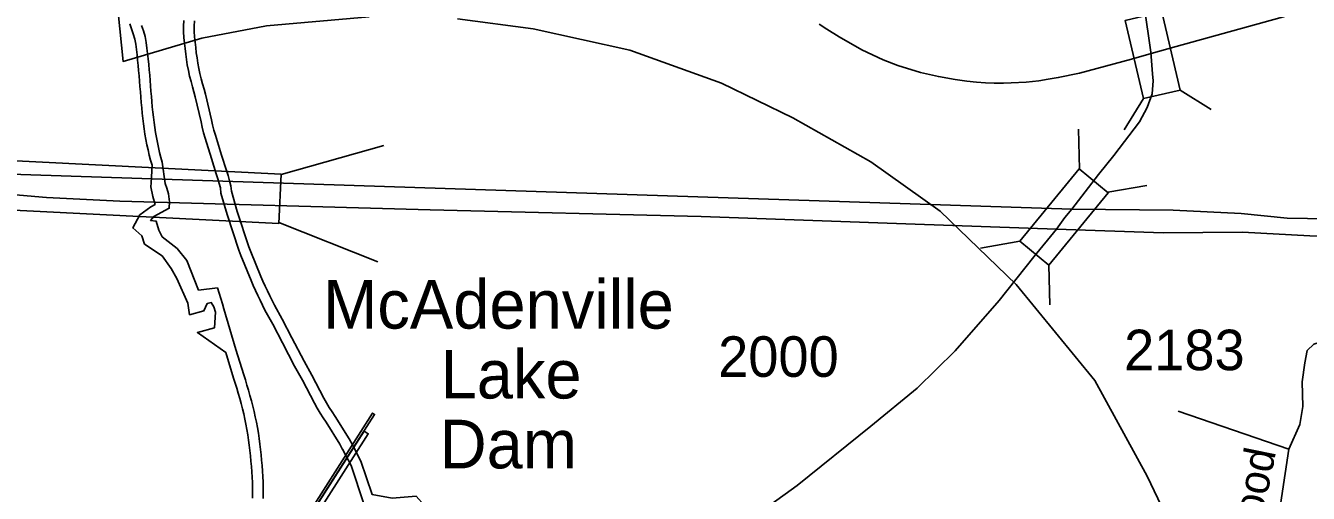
# Model space of a CAD drawing. Extents: x 1364363 to 1407445, y 538563 to 573342.
# Drawn here: x 1379352 to 1383308, y 556667 to 558110 of the extents above; entities that cross this region are included whole.
import ezdxf

# ---------------------------------------------------------------- set-up
doc = ezdxf.new("R2010")
doc.units = 0
for name, color, linetype in [('Exist Boundary Political City Limit New', 7, 'Continuous'), ('Exist Hydrographic Buffer Line', 7, 'Continuous'), ('Exist Hydrographic Creek Double Shore', 7, 'Continuous'), ('Exist Hydrographic Lake Dam', 7, 'Continuous'), ('Exist Railroad Mainline', 7, 'Continuous'), ('Exist Road Primary Interstate Divided Center Attributed', 7, 'Continuous'), ('Exist Road Primary Interstate Structure Standard Bridge CELL', 7, 'Continuous'), ('Exist Road Secondary Structure Standard Bridge CELL', 7, 'Continuous'), ('Exist Road Secondary Type 51 Attributed', 7, 'Continuous'), ('Exist Road Secondary Type 51 Label', 7, 'Continuous'), ('Exist Road Secondary Type 51 Number Label', 7, 'Continuous')]:
    doc.layers.add(name, color=color, linetype=linetype)

msp = doc.modelspace()

# ---------------------------------------------------------------- linework, layer by layer
at = {"layer": 'Exist Boundary Political City Limit New'}
for points in [[(1379628.6, 558241.4), (1379652.8, 557999.4), (1379895.8, 558071.1), (1380094.6, 558108.9), (1380411.5, 558136.3)], [(1380683.5, 558130.6), (1380917, 558099.8), (1381215.6, 558033.5), (1381497.8, 557931.8), (1381717.6, 557825.1), (1381958.9, 557689.9), (1382171.9, 557537.4), (1382407.2, 557310.6), (1382649.2, 557015.3), (1382811.1, 556719.8), (1382951.1, 556424.8), (1383046.6, 556108.5), (1383105.9, 555785.2), (1383120, 555490.8), (1383095.2, 555175.1)]]:
    msp.add_lwpolyline(points, dxfattribs=at)
at = {"layer": 'Exist Hydrographic Buffer Line'}
for points in [[(1379709.6, 558110.4), (1379715.3, 558094), (1379720.8, 558075.8), (1379724.1, 558057.2), (1379726.4, 558040), (1379728.4, 558023.3), (1379730.2, 558006.7), (1379731.9, 557990.2), (1379733.4, 557973.5), (1379734.8, 557957), (1379736.1, 557940.6), (1379737.4, 557924.2), (1379738.8, 557907.8), (1379740.1, 557891.5), (1379741.4, 557875.3), (1379742.9, 557859.2), (1379744.5, 557843.1), (1379746.3, 557827.1), (1379748.2, 557811.2), (1379750.2, 557795.4), (1379752.6, 557780), (1379755.3, 557764.5), (1379758.4, 557748.9), (1379761.7, 557733.5), (1379765.4, 557718.1), (1379769.3, 557703), (1379773.4, 557688.8), (1379782.2, 557622.5), (1379787.9, 557608.5), (1379793.1, 557591.1), (1379796.4, 557566), (1379795.3, 557546), (1379747.4, 557521.2), (1379737.6, 557508.5), (1379754.4, 557506.5), (1379763, 557478.7), (1379773, 557458.1), (1379819.1, 557421.8), (1379849.1, 557385.3), (1379885.7, 557293.7), (1379943.5, 557300.7), (1379949.4, 557284.1), (1379954.6, 557267.4), (1379959.3, 557251.2), (1379963.7, 557235.4), (1379982, 557172.7), (1380000.7, 557110.3), (1380024.7, 557032.2), (1380029.8, 557016.5), (1380034.7, 557000.5), (1380039.5, 556984.5), (1380044.1, 556968.4), (1380048.5, 556952.1), (1380052.7, 556935.8), (1380056.8, 556919.3), (1380060.5, 556902.7), (1380063.9, 556886.1), (1380067.1, 556869.4), (1380069.9, 556852.5), (1380072.3, 556835.6), (1380074.4, 556818.9), (1380076.4, 556802.2), (1380078.1, 556785.6), (1380079.7, 556769.1), (1380081.3, 556752.6), (1380082.8, 556735.6), (1380083.7, 556718.4), (1380084.4, 556701.3), (1380084.6, 556684.4), (1380084.7, 556667.8), (1380084.7, 556651.1)], [(1379839.9, 558125.4), (1379839.3, 558108.3), (1379839.5, 558090.5), (1379840.5, 558072.7), (1379842.1, 558055.4), (1379844, 558038.7), (1379846, 558022.1), (1379848.2, 558005.3), (1379850.8, 557988.2), (1379854, 557970.9), (1379857.9, 557953.7), (1379862.2, 557937.3), (1379866.4, 557921.3), (1379870.8, 557905.2), (1379875, 557889.8), (1379893.6, 557812.5), (1379896.3, 557796.2), (1379901.2, 557778.4), (1379906.1, 557762.2), (1379925.4, 557699.7), (1379940.3, 557652.7), (1379945.1, 557637.4), (1379949.5, 557622.6), (1379952.7, 557609.5), (1379954.6, 557592.5), (1379973.6, 557526.6), (1380009.8, 557416.7), (1380015.6, 557400.1), (1380047.4, 557323.2), (1380054.2, 557307.8), (1380061.1, 557292.5), (1380068.1, 557277.3), (1380075.3, 557262.2), (1380082.5, 557247.2), (1380090.3, 557231.4), (1380114.6, 557188.9), (1380144.1, 557131.4), (1380181.8, 557058.6), (1380205.7, 557015.5), (1380243, 556944.8), (1380251.1, 556929.5), (1380260.2, 556914.3), (1380269.7, 556899.7), (1380278.8, 556886.3), (1380321.3, 556818.3), (1380329.8, 556802.4)], [(1381262.6, 555900.5), (1381213.8, 555976.4), (1381107.2, 556071.9), (1381035.1, 556160.7), (1380901, 556244.5), (1380797.6, 556336.5), (1380656.5, 556442.3), (1380581.1, 556581.7), (1380543.3, 556623.7), (1380481.3, 556618.9), (1380395.5, 556634.5), (1380356.1, 556752.7), (1380329.8, 556802.5)]]:
    msp.add_lwpolyline(points, dxfattribs=at)
at = {"layer": 'Exist Hydrographic Creek Double Shore'}
for points in [[(1379673.2, 558115), (1379678.7, 558099.4), (1379684.1, 558083.9), (1379688.8, 558068.2), (1379691.7, 558052.1), (1379693.9, 558035.9), (1379695.8, 558019.6), (1379697.6, 558003.3), (1379699.2, 557987), (1379700.7, 557970.7), (1379702.1, 557954.3), (1379703.4, 557937.9), (1379704.7, 557921.5), (1379706.1, 557905.1), (1379707.4, 557888.8), (1379708.7, 557872.4), (1379710.3, 557856), (1379711.9, 557839.7), (1379713.7, 557823.4), (1379715.6, 557807.1), (1379717.8, 557790.8), (1379720.2, 557774.6), (1379723.1, 557758.4), (1379726.3, 557742.3), (1379729.7, 557726.2), (1379733.5, 557710.2), (1379737.6, 557694.4), (1379742.2, 557678.7), (1379739.3, 557624.5), (1379738.1, 557612.7), (1379744.5, 557582.2), (1379751.5, 557557.6), (1379738.7, 557550.3), (1379704.7, 557525.8), (1379682.4, 557485.7), (1379710.8, 557461.4), (1379718.6, 557435.8), (1379773.8, 557399), (1379801.1, 557360), (1379818.9, 557329.3), (1379852.9, 557253.9), (1379857.9, 557217.7), (1379901.9, 557229.4), (1379911.9, 557252.2), (1379924.7, 557255), (1379932.8, 557241.6), (1379937.3, 557225.9), (1379934.4, 557177.5), (1379882, 557162.5), (1379969.4, 557100.8), (1379993.4, 557022.3), (1379998.5, 557006.7), (1380003.3, 556991), (1380008, 556975.3), (1380012.5, 556959.5), (1380016.8, 556943.7), (1380020.9, 556927.8), (1380024.8, 556911.9), (1380028.4, 556895.8), (1380031.7, 556879.7), (1380034.8, 556863.6), (1380037.4, 556847.4), (1380039.8, 556831.2), (1380041.8, 556814.9), (1380043.8, 556798.6), (1380045.4, 556782.3), (1380047.1, 556765.9), (1380048.6, 556749.6), (1380050, 556733.3), (1380051, 556716.9), (1380051.6, 556700.5), (1380051.8, 556684.1), (1380051.9, 556667.7), (1380051.9, 556651.3)], [(1379872.7, 558124.3), (1379872.2, 558107.9), (1379872.3, 558091.5), (1379873.2, 558075.1), (1379874.7, 558058.8), (1379876.6, 558042.5), (1379878.5, 558026.2), (1379880.7, 558009.9), (1379883.1, 557993.7), (1379886.1, 557977.5), (1379889.8, 557961.5), (1379893.9, 557945.6), (1379898.1, 557929.8), (1379902.4, 557913.9), (1379906.8, 557898.1), (1379925.8, 557819), (1379928.3, 557803.3), (1379932.8, 557787.5), (1379937.5, 557771.7), (1379956.7, 557709.5), (1379971.6, 557662.6), (1379976.5, 557646.9), (1379981.1, 557631.1), (1379985, 557615.3), (1379986.9, 557598.9), (1380004.9, 557536.3), (1380040.9, 557427.2), (1380046.2, 557411.7), (1380077.6, 557336.1), (1380084.2, 557321.1), (1380090.9, 557306.1), (1380097.8, 557291.2), (1380104.9, 557276.3), (1380112, 557261.5), (1380119.2, 557246.8), (1380143.4, 557204.5), (1380173.3, 557146.5), (1380210.7, 557074.1), (1380234.6, 557031.1), (1380272, 556960.2), (1380279.7, 556945.7), (1380288.1, 556931.6), (1380297, 556917.8), (1380306.3, 556904.2), (1380349.7, 556834.7), (1380358.7, 556817.9)], [(1381290.2, 555918.3), (1381239, 555997.9), (1381131, 556094.6), (1381057.1, 556185.6), (1380920.7, 556270.9), (1380818.4, 556361.9), (1380682, 556464.3), (1380608.1, 556600.8), (1380556.9, 556657.6), (1380483, 556652), (1380420.5, 556663.3), (1380386.4, 556765.7), (1380358.7, 556817.9)]]:
    msp.add_lwpolyline(points, dxfattribs=at)
at = {"layer": 'Exist Hydrographic Lake Dam'}
for points in [[(1380029.7, 556285.2), (1380428.4, 556910.3), (1380422.2, 556914.3), (1380023.6, 556289.1)], [(1380062.5, 556336.5), (1380395.7, 556859), (1380409, 556850.5), (1380075.8, 556328)]]:
    msp.add_lwpolyline(points, close=True, dxfattribs=at)
at = {"layer": 'Exist Railroad Mainline'}
msp.add_lwpolyline([(1381799.6, 558114.6), (1381822.7, 558098.5), (1381861.2, 558075.3), (1381930.3, 558035.1), (1381996.6, 558004.4), (1382042, 557987.1), (1382111.6, 557965.4), (1382166.8, 557952.6), (1382219.1, 557943.2), (1382254.8, 557938.6), (1382284.9, 557935.2), (1382312.3, 557933.1), (1382338.5, 557932.3), (1382367.7, 557932.6), (1382391.7, 557933.1), (1382437.4, 557935.5), (1382477, 557939.8), (1382505.3, 557944.1), (1382536.6, 557949.5), (1382601.5, 557963.3), (1382762, 558006.2), (1382823, 558023.5), (1382900.5, 558045.5), (1383267.6, 558147.2)], dxfattribs=at)
at = {"layer": 'Exist Road Primary Interstate Divided Center Attributed'}
for points in [[(1382578.3, 557543.3), (1378993.5, 557662), (1378353.6, 557700.7), (1377951.9, 557715.7), (1377613, 557708.6)], [(1378009.8, 557639.5), (1378088.7, 557639.5), (1378267.6, 557630.8), (1379261.7, 557592.6), (1379417.1, 557579), (1379642.8, 557567.9)], [(1379642.8, 557567.9), (1380599.9, 557541.4), (1381435, 557521.1), (1382094.8, 557497), (1382531.5, 557481.6)], [(1385949.5, 557261.4), (1385838.7, 557297.2), (1385700.2, 557335.7), (1385555.5, 557374.9), (1385363.2, 557413.7), (1385252.4, 557436.1), (1385141.6, 557451), (1385049.2, 557464.5), (1384710.8, 557467.7), (1384340.5, 557484.4), (1383867.5, 557505.6), (1383242.8, 557515.9), (1383100.7, 557529.7), (1382890.4, 557540.7), (1382578.3, 557543.3)], [(1382531.5, 557481.6), (1382859.6, 557470.5), (1383105.1, 557472.7), (1383312.1, 557460.7), (1383713, 557449.7), (1383905.8, 557445.3), (1384433.1, 557402.9), (1384673, 557367.4), (1384806.8, 557349.5), (1384968.4, 557322.6), (1385057.7, 557304.7), (1385197, 557267.4), (1385401.7, 557212.1), (1385543.2, 557173.3), (1385689.4, 557131.5), (1385878, 557074.8)]]:
    msp.add_lwpolyline(points, dxfattribs=at)
at = {"layer": 'Exist Road Primary Interstate Structure Standard Bridge CELL'}
for p, q in [((1380140.6, 557650.2), (1380456.5, 557739.5)), ((1380133.1, 557501.9), (1380438.5, 557381.4))]:
    msp.add_line(p, q, dxfattribs=at)
msp.add_lwpolyline([(1379178.3, 557699.3), (1380140.6, 557650.9), (1380133, 557499.1), (1379170.7, 557547.5)], close=True, dxfattribs=at)
at = {"layer": 'Exist Road Secondary Structure Standard Bridge CELL'}
for p, q in [((1383008.4, 557851.2), (1382912.3, 557910.9)), ((1382739.8, 557788.4), (1382799.5, 557884.6)), ((1382601.6, 557667.3), (1382598.9, 557790.1)), ((1382689.1, 557595.4), (1382810.1, 557616.7)), ((1382296.9, 557423.3), (1382417.9, 557444.5)), ((1382510.1, 557248.2), (1382507.4, 557371))]:
    msp.add_line(p, q, dxfattribs=at)
for points in [[(1382799.5, 557884.6), (1382743.1, 558125.9), (1382855.8, 558152.3), (1382912.3, 557910.9)], [(1382417.9, 557444.5), (1382601.2, 557667.6), (1382690.7, 557594.1), (1382507.4, 557371)]]:
    msp.add_lwpolyline(points, close=True, dxfattribs=at)
at = {"layer": 'Exist Road Secondary Type 51 Attributed'}
msp.add_line((1383247.8, 556802.5), (1382906.4, 556920.2), dxfattribs=at)
for points in [[(1383043.1, 558745), (1382902.7, 558466.2), (1382857.4, 558403.1), (1382827.2, 558354.8), (1382799, 558262.7), (1382795.6, 558216), (1382800.9, 558170.5), (1382822.4, 558028.1)], [(1382822.4, 558028.1), (1382827.5, 557960.9), (1382829, 557939.8), (1382825.6, 557899.1), (1382810.2, 557857.2), (1382786.8, 557812.8), (1382707.8, 557709.1), (1382660.4, 557650.3), (1382578.3, 557543.3)], [(1382578.3, 557543.3), (1382556.8, 557518), (1382531.5, 557481.6)], [(1382531.5, 557481.6), (1382461.2, 557395.9), (1382354.5, 557261.4), (1382218.8, 557106.6), (1382101.9, 556991.2), (1381958.6, 556873.5), (1381731.6, 556691), (1381381.1, 556437.4), (1381163.3, 556298.4)], [(1383247.8, 556802.5), (1383281.3, 556879.3), (1383290.4, 556935.1), (1383288.9, 557010.6), (1383296.4, 557069.5), (1383303.9, 557106.9), (1383324.2, 557127.3), (1383367.4, 557140.6), (1383442.7, 557129.1), (1383737, 557113.9)], [(1382963.8, 556162.4), (1383079.1, 556222.1), (1383114.2, 556247.1), (1383132.1, 556272.9), (1383151.7, 556315), (1383174.3, 556382.1), (1383210.1, 556557.4), (1383247.8, 556802.5)]]:
    msp.add_lwpolyline(points, dxfattribs=at)

# ---------------------------------------------------------------- texts
at = {"layer": 'Exist Hydrographic Lake Dam'}
for s, p in [('McAdenville', (1380269.7, 557174.9)), ('Lake', (1380631.7, 556959.3)), ('Dam', (1380629, 556743.7))]:
    msp.add_text(s, height=150, dxfattribs=at).set_placement(p)
at = {"layer": 'Exist Road Secondary Type 51 Label'}
msp.add_text('Beechwood', height=95, rotation=78.4782, dxfattribs=at).set_placement((1383075.8, 556145.2))
at = {"layer": 'Exist Road Secondary Type 51 Number Label'}
for s, p in [('2000', (1381487.7, 557026.1)), ('2183', (1382739.5, 557046.6))]:
    msp.add_text(s, height=125, dxfattribs=at).set_placement(p)

doc.saveas('drawing.dxf')
